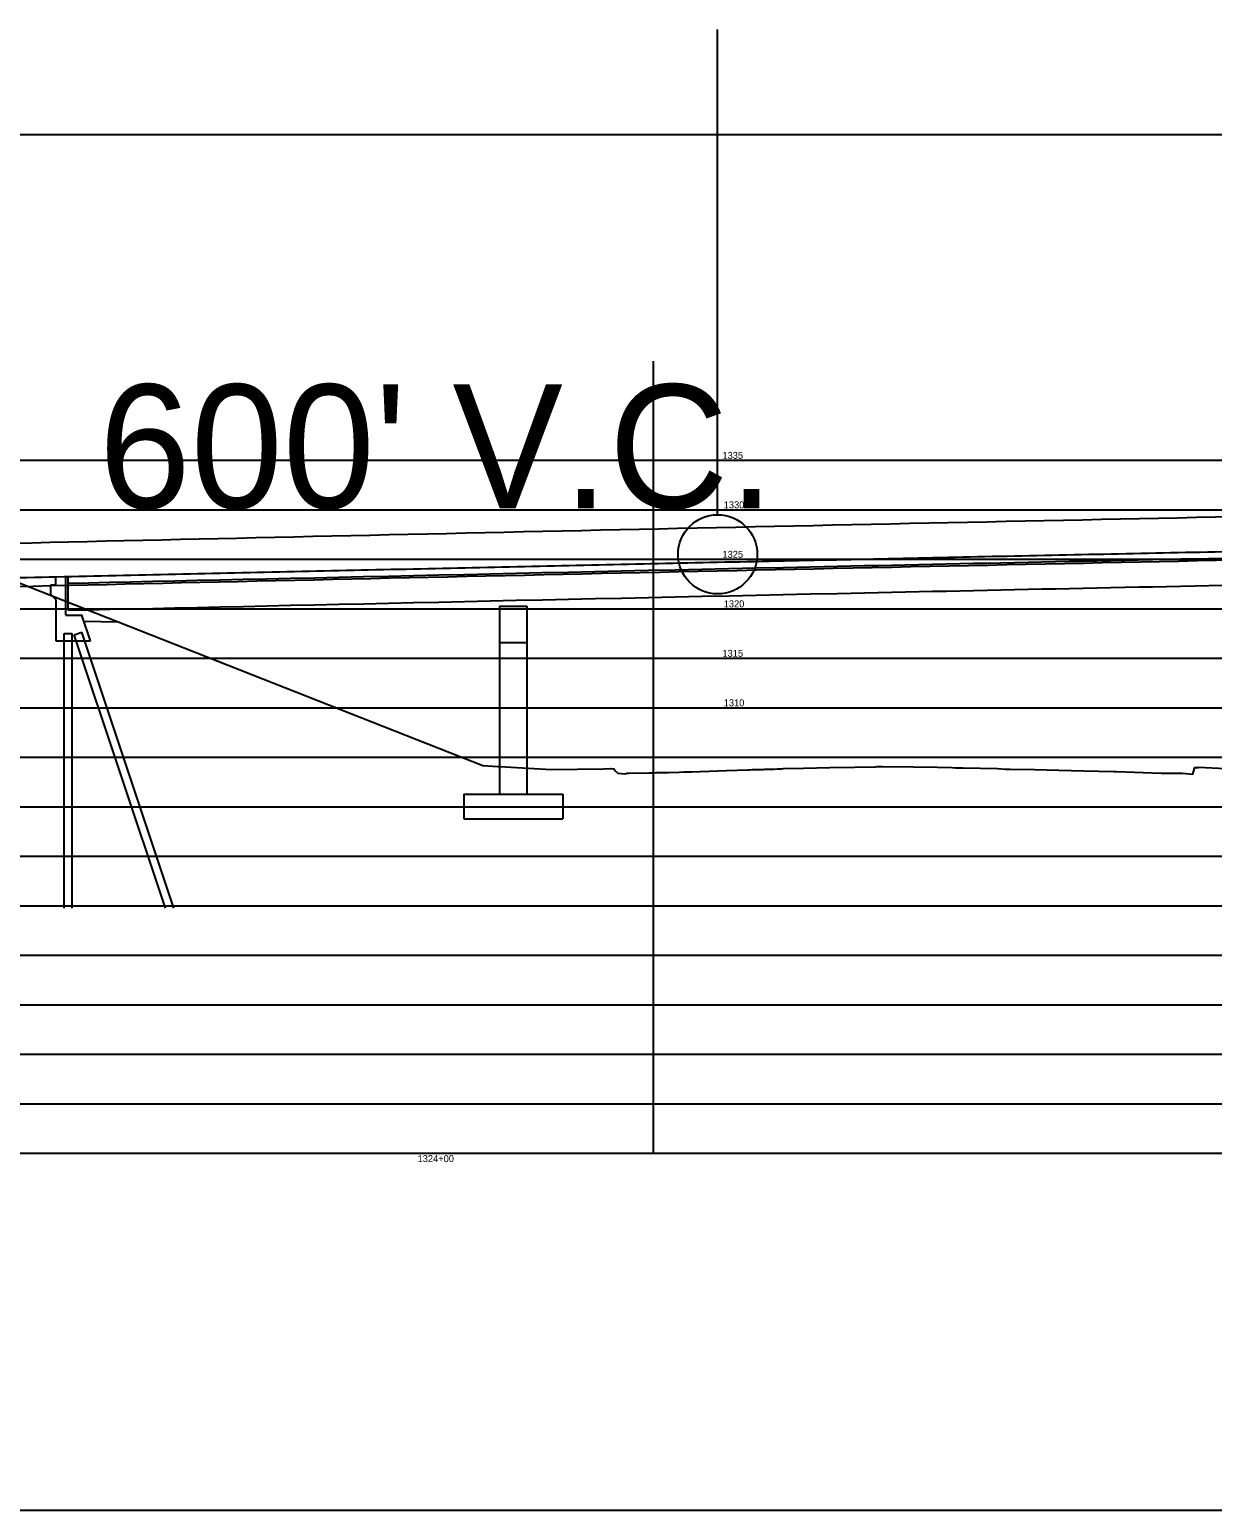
# Model space of a CAD drawing. Extents: x 680639 to 702326, y 743523 to 756592.
# Drawn here: x 688562.8 to 688682.2, y 751717.1 to 751866.7 of the extents above; entities that cross this region are included whole.
import ezdxf

# ---------------------------------------------------------------- set-up
doc = ezdxf.new("R2010")
doc.units = 0
for name, color, linetype in [('B_Concrete', 7, 'Continuous'), ('B_Existing Structure', 7, 'Continuous'), ('B_Proposed Ground', 7, 'Continuous'), ('B_Steel', 7, 'Continuous'), ('Default', 7, 'Continuous'), ('R_Axis', 7, 'Continuous'), ('R_Axis Annot', 7, 'Continuous'), ('R_Exist Surface', 7, 'Continuous'), ('R_No Plot', 7, 'Continuous'), ('R_Vert Alg', 7, 'Continuous')]:
    doc.layers.add(name, color=color, linetype=linetype)

msp = doc.modelspace()

# ---------------------------------------------------------------- linework, layer by layer
at = {"layer": 'B_Concrete'}
for p, q in [((688565.4, 751810.62), (688565.4, 751811.41)), ((688566.4, 751807.53), (688566.4, 751811.44)), ((688564.9, 751809.62), (688564.9, 751810.62)), ((688564.9, 751810.62), (688565.4, 751810.62)), ((688565.4, 751809.12), (688564.9, 751809.62)), ((688565.4, 751809.12), (688565.4, 751804.95)), ((688566.4, 751807.53), (688568.06, 751807.53)), ((688568.06, 751807.45), (688568.06, 751807.53)), ((688568.9, 751804.95), (688568.06, 751807.45)), ((688565.4, 751804.95), (688568.9, 751804.95))]:
    msp.add_line(p, q, dxfattribs=at)
msp.add_open_spline([(688372.96, 751810.2), (688384.35, 751810.5), (688420.74, 751811.44), (688507.13, 751813.6), (688632.13, 751816.46), (688757.14, 751819), (688844.65, 751820.6), (688882.16, 751821.24), (688897.6, 751821.51), (688900.54, 751821.56), (688903.48, 751821.61)], degree=3, dxfattribs=at)
at = {"layer": 'B_Existing Structure'}
for p, q in [((688610.21, 751808.45), (688610.21, 751789.47)), ((688610.21, 751808.45), (688612.96, 751808.45)), ((688612.96, 751808.45), (688612.96, 751789.47)), ((688610.21, 751804.78), (688612.96, 751804.78)), ((688606.59, 751789.47), (688616.59, 751789.47)), ((688606.59, 751789.47), (688606.59, 751786.97)), ((688616.59, 751789.47), (688616.59, 751786.97)), ((688606.59, 751786.97), (688616.59, 751786.97))]:
    msp.add_line(p, q, dxfattribs=at)
at = {"layer": 'B_Proposed Ground'}
msp.add_line((688568.23, 751806.95), (688571.68, 751806.87), dxfattribs=at)
msp.add_open_spline([(688372.96, 751805.82), (688384.39, 751806.12), (688420.81, 751807.06), (688507.23, 751809.22), (688632.23, 751812.08), (688757.23, 751814.62), (688844.73, 751816.22), (688882.24, 751816.87), (688897.65, 751817.13), (688900.57, 751817.18), (688903.48, 751817.23)], degree=3, dxfattribs=at)
at = {"layer": 'B_Steel'}
for p, q in [((688566.65, 751808.04), (688566.65, 751811.44)), ((688566.24, 751777.95), (688566.24, 751805.7)), ((688566.24, 751805.7), (688567.05, 751805.7)), ((688567.05, 751777.95), (688567.05, 751805.7)), ((688567.26, 751805.57), (688568.03, 751805.82)), ((688576.47, 751777.95), (688567.26, 751805.57)), ((688577.32, 751777.95), (688568.03, 751805.82))]:
    msp.add_line(p, q, dxfattribs=at)
for points in [[(688566.65, 751810.77), (688588.51, 751811.27), (688647.06, 751812.57), (688705.62, 751813.78), (688742.32, 751814.5)], [(688566.65, 751808.04), (688588.52, 751808.53), (688647.08, 751809.83), (688705.64, 751811.04), (688742.32, 751811.76)]]:
    msp.add_open_spline(points, degree=3, dxfattribs=at)
at = {"layer": 'Default'}
msp.add_line((688632.23, 751817.69), (688632.23, 751866.7), dxfattribs=at)
msp.add_circle((688632.23, 751813.69), 4, dxfattribs=at)
at = {"layer": 'R_Axis'}
for p, q in [((688625.74, 751753.19), (688625.74, 751833.19)), ((688372.96, 751823.19), (688903.48, 751823.19)), ((688372.96, 751818.19), (688903.48, 751818.19)), ((688372.96, 751813.19), (688903.48, 751813.19)), ((688372.96, 751808.19), (688903.48, 751808.19)), ((688372.96, 751803.19), (688903.48, 751803.19)), ((688372.96, 751798.19), (688903.48, 751798.19)), ((688372.96, 751793.19), (688903.48, 751793.19)), ((688372.96, 751788.19), (688903.48, 751788.19)), ((688372.96, 751783.19), (688903.48, 751783.19)), ((688372.96, 751778.19), (688903.48, 751778.19)), ((688372.96, 751773.19), (688903.48, 751773.19)), ((688372.96, 751768.19), (688903.48, 751768.19)), ((688372.96, 751763.19), (688903.48, 751763.19)), ((688372.96, 751758.19), (688903.48, 751758.19)), ((688372.96, 751753.19), (688903.48, 751753.19))]:
    msp.add_line(p, q, dxfattribs=at)
at = {"layer": 'R_Exist Surface'}
msp.add_line((688560.6, 751811.24), (688608.52, 751792.37), dxfattribs=at)
msp.add_lwpolyline([(688358.07, 751856.12), (688913.85, 751856.12), (688913.85, 751717.1), (688358.07, 751717.1)], close=True, dxfattribs=at)
msp.add_lwpolyline([(688608.52, 751792.37), (688610.02, 751792.27), (688610.23, 751792.27), (688615.42, 751791.95), (688620.71, 751792.03), (688621.42, 751792.06), (688621.47, 751792.05), (688621.75, 751792.01), (688621.81, 751791.9), (688622.15, 751791.57), (688622.9, 751791.52), (688623.07, 751791.58), (688623.2, 751791.58), (688623.3, 751791.58), (688625.28, 751791.61), (688625.45, 751791.62), (688625.53, 751791.62), (688625.86, 751791.63), (688626.02, 751791.64), (688626.96, 751791.65), (688627.08, 751791.65), (688627.27, 751791.65), (688628.35, 751791.68), (688628.83, 751791.7), (688629.14, 751791.7), (688629.29, 751791.7), (688629.6, 751791.72), (688633.12, 751791.86), (688635.31, 751791.92), (688635.5, 751791.92), (688635.72, 751791.94), (688636.61, 751791.96), (688636.83, 751791.96), (688636.99, 751791.97), (688637.31, 751791.99), (688637.47, 751791.99), (688637.79, 751792), (688637.9, 751792), (688638.26, 751792.01), (688638.67, 751792.01), (688638.9, 751792.04), (688640.91, 751792.08), (688643.58, 751792.14), (688646.07, 751792.2), (688648.2, 751792.23), (688648.36, 751792.24), (688648.86, 751792.24), (688651.97, 751792.22), (688654.45, 751792.19), (688655.92, 751792.14), (688656.26, 751792.13), (688657.02, 751792.12), (688660.49, 751792.04), (688661.28, 751791.99), (688661.76, 751792), (688664.24, 751791.94), (688666.68, 751791.87), (688669.17, 751791.81), (688672.24, 751791.74), (688672.53, 751791.74), (688677.02, 751791.59), (688677.26, 751791.59), (688679.14, 751791.58), (688679.14, 751791.58), (688679.15, 751791.58), (688680.22, 751791.47), (688680.39, 751792.04), (688680.44, 751792.14), (688680.75, 751792.17), (688680.83, 751792.18), (688686.16, 751791.91)], dxfattribs=at)
at = {"layer": 'R_Vert Alg'}
msp.add_spline([(688372.96, 751806.7), (688380.23, 751806.89), (688392.23, 751807.2), (688404.23, 751807.51), (688416.23, 751807.82), (688428.23, 751808.12), (688440.23, 751808.42), (688452.23, 751808.72), (688464.23, 751809.02), (688476.23, 751809.31), (688488.23, 751809.6), (688500.23, 751809.89), (688512.23, 751810.18), (688524.23, 751810.46), (688536.23, 751810.74), (688548.23, 751811.02), (688560.23, 751811.3), (688572.23, 751811.57), (688584.23, 751811.84), (688596.23, 751812.11), (688608.23, 751812.37), (688620.23, 751812.64), (688632.23, 751812.9), (688644.23, 751813.15), (688656.23, 751813.41), (688668.23, 751813.66), (688680.23, 751813.91), (688692.23, 751814.16), (688704.23, 751814.41), (688716.23, 751814.65), (688728.23, 751814.89), (688740.23, 751815.13), (688752.23, 751815.36), (688764.23, 751815.59), (688776.23, 751815.82), (688788.23, 751816.05), (688800.23, 751816.28), (688812.23, 751816.5), (688824.23, 751816.72), (688836.23, 751816.93), (688848.23, 751817.15), (688860.23, 751817.36), (688872.23, 751817.57), (688884.23, 751817.78), (688896.23, 751817.98), (688903.48, 751818.11)], degree=3, dxfattribs=at)

# ---------------------------------------------------------------- texts
at = {"layer": 'Default'}
msp.add_text("600' V.C. ", height=12.5, dxfattribs=at).set_placement((688569.73, 751818.35))
at = {"layer": 'R_Axis Annot'}
msp.add_text('1324+00', height=0.7, dxfattribs=at).set_placement((688601.93, 751752.29))
at = {"layer": 'R_No Plot'}
for s, p in [('1335', (688632.72, 751823.34)), ('1330', (688632.85, 751818.34)), ('1325', (688632.72, 751813.34)), ('1320', (688632.85, 751808.34)), ('1315', (688632.72, 751803.34)), ('1310', (688632.85, 751798.34))]:
    msp.add_text(s, height=0.7, dxfattribs=at).set_placement(p)

doc.saveas('drawing.dxf')
